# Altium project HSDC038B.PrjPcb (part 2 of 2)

## Sheet HSDC038B_Magnetics.SchDoc
size 431 x 279 mm; Date: Not shown in title block; ApprovedBy: Not shown in title block; CheckedBy: Not shown in title block; Author: Not shown in title block; CompanyName: Not shown in title block; Engineer: Not shown in title block; Organization: Not shown in title block; Address1: Not shown in title block; Address2: Not shown in title block; Address3: Not shown in title block; Address4: Not shown in title block; DocumentNumber: 4; Revision: Use project parameter SCH_Rev; SheetNumber: 4; SheetTotal: 7; PageSetup: Record=PageOptions¦CenterHorizontal=True¦CenterVertical=True¦PrintScale=1.00¦XCorrection=1.00¦YCorrection=1.00¦PrintKind=0¦BorderSize=5000000¦LeftOffset=0¦BottomOffset=0¦Orientation=2¦PaperLength=1000¦PaperWidth=1000¦Scale=100¦PaperSource=15¦PrintQuality=600¦MediaType=1¦DitherType=10¦PaperKind=Letter¦PrintScaleMode=1
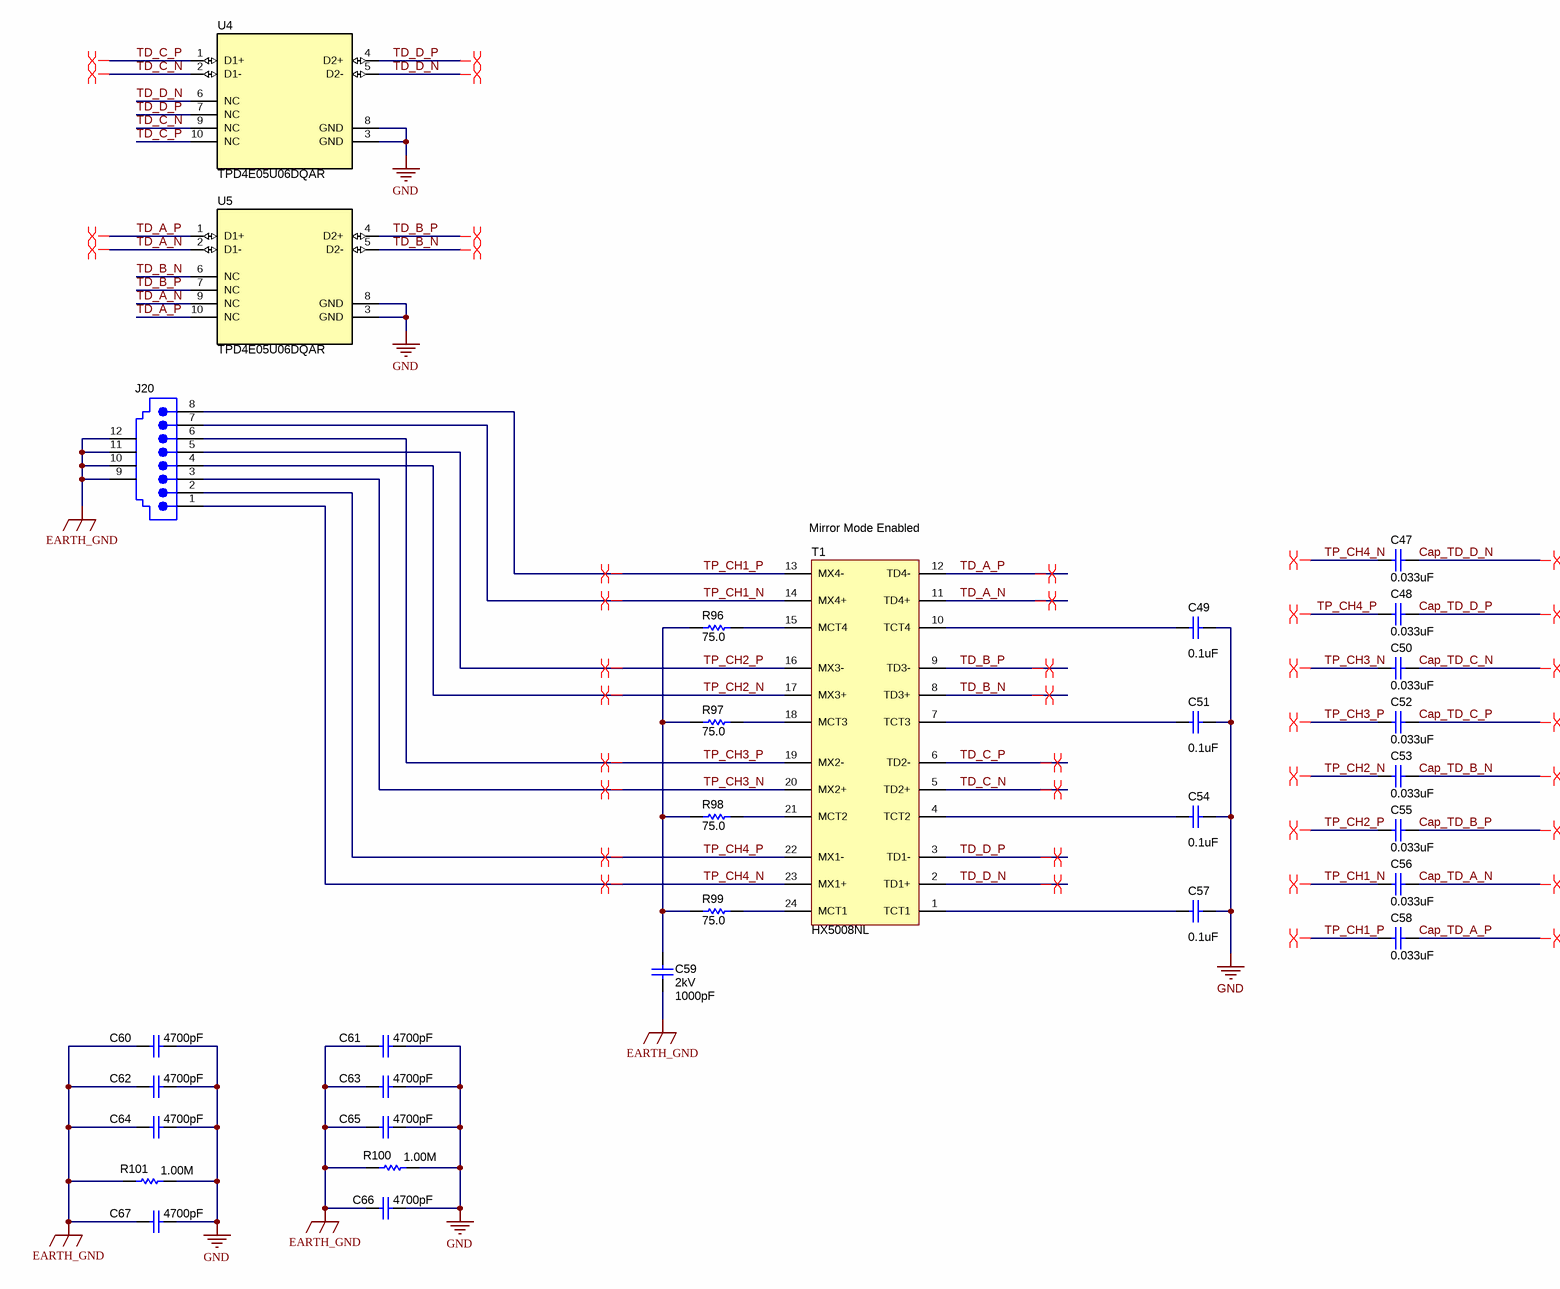
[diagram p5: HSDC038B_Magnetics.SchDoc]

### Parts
C47  ValueDisplayed: 0.033uF  [0402L]  (hidden comment: GRM155R61A333KA01D)
C48  ValueDisplayed: 0.033uF  [0402L]  (hidden comment: GRM155R61A333KA01D)
C49  ValueDisplayed: 0.1uF  [0603]  (hidden comment: C0603C104K8RACTU)
C50  ValueDisplayed: 0.033uF  [0402L]  (hidden comment: GRM155R61A333KA01D)
C51  ValueDisplayed: 0.1uF  [0603]  (hidden comment: C0603C104K8RACTU)
C52  ValueDisplayed: 0.033uF  [0402L]  (hidden comment: GRM155R61A333KA01D)
C53  ValueDisplayed: 0.033uF  [0402L]  (hidden comment: GRM155R61A333KA01D)
C54  ValueDisplayed: 0.1uF  [0603]  (hidden comment: C0603C104K8RACTU)
C55  ValueDisplayed: 0.033uF  [0402L]  (hidden comment: GRM155R61A333KA01D)
C56  ValueDisplayed: 0.033uF  [0402L]  (hidden comment: GRM155R61A333KA01D)
C57  ValueDisplayed: 0.1uF  [0603]  (hidden comment: C0603C104K8RACTU)
C58  ValueDisplayed: 0.033uF  [0402L]  (hidden comment: GRM155R61A333KA01D)
C59  VDC_V: 2kV  ValueDisplayed: 1000pF  [1808]  (hidden comment: GR442QR73D102KW01L)
C60  ValueDisplayed: 4700pF  [1812_254]  (hidden comment: 1812GC472KAT1A)
C61  ValueDisplayed: 4700pF  [1812_254]  (hidden comment: 1812GC472KAT1A)
C62  ValueDisplayed: 4700pF  [1812_254]  (hidden comment: 1812GC472KAT1A)
C63  ValueDisplayed: 4700pF  [1812_254]  (hidden comment: 1812GC472KAT1A)
C64  ValueDisplayed: 4700pF  [1812_254]  (hidden comment: 1812GC472KAT1A)
C65  ValueDisplayed: 4700pF  [1812_254]  (hidden comment: 1812GC472KAT1A)
C66  ValueDisplayed: 4700pF  [1812_254]  (hidden comment: 1812GC472KAT1A)
C67  ValueDisplayed: 4700pF  [1812_254]  (hidden comment: 1812GC472KAT1A)
J20  1-406541-1  [TEC_1-406541-1]  (value not drawn)
R96  ValueDisplayed: 75.0  [0805_HV]  (hidden comment: CRCW080575R0FKEA)
R97  ValueDisplayed: 75.0  [0805_HV]  (hidden comment: CRCW080575R0FKEA)
R98  ValueDisplayed: 75.0  [0805_HV]  (hidden comment: CRCW080575R0FKEA)
R99  ValueDisplayed: 75.0  [0805_HV]  (hidden comment: CRCW080575R0FKEA)
R100  ValueDisplayed: 1.00M  [2010]  (hidden comment: HVCB2010FKC1M00)
R101  ValueDisplayed: 1.00M  [2010]  (hidden comment: HVCB2010FKC1M00)
T1  HX5008NL  [PULSE_HX5008NL]
U4  TPD4E05U06DQAR  [DQA0010A]
U5  TPD4E05U06DQAR  [DQA0010A]

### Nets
EARTH_GND: C59.2 C60.2 C61.2 C62.2 C63.2 C64.2 C65.2 C66.2 C67.2 J20.9 J20.10 J20.11 J20.12 R100.1 R101.1
GND: C49.1 C51.1 C54.1 C57.1 C60.1 C61.1 C62.1 C63.1 C64.1 C65.1 C66.1 C67.1 R100.2 R101.2 U4.3(GND) U4.8(GND) U5.3(GND) U5.8(GND)
Cap_TD_A_N: C56.2
Cap_TD_A_P: C58.2
Cap_TD_B_N: C53.2
Cap_TD_B_P: C55.2
Cap_TD_C_N: C50.2
Cap_TD_C_P: C52.2
Cap_TD_D_N: C47.2
Cap_TD_D_P: C48.2
TD_A_N: T1.11(TD4+) U5.2(D1-) U5.9(NC)
TD_A_P: T1.12(TD4-) U5.1(D1+) U5.10(NC)
TD_B_N: T1.8(TD3+) U5.5(D2-) U5.6(NC)
TD_B_P: T1.9(TD3-) U5.4(D2+) U5.7(NC)
TD_C_N: T1.5(TD2+) U4.2(D1-) U4.9(NC)
TD_C_P: T1.6(TD2-) U4.1(D1+) U4.10(NC)
TD_D_N: T1.2(TD1+) U4.5(D2-) U4.6(NC)
TD_D_P: T1.3(TD1-) U4.4(D2+) U4.7(NC)
TP_CH1_N: C56.1 J20.7 T1.14(MX4+)
TP_CH1_P: C58.1 J20.8 T1.13(MX4-)
TP_CH2_N: C53.1 J20.4 T1.17(MX3+)
TP_CH2_P: C55.1 J20.5 T1.16(MX3-)
TP_CH3_N: C50.1 J20.3 T1.20(MX2+)
TP_CH3_P: C52.1 J20.6 T1.19(MX2-)
TP_CH4_N: C47.1 J20.1 T1.23(MX1+)
TP_CH4_P: C48.1 J20.2 T1.22(MX1-)
NetC49_2: C49.2 T1.10(TCT4)
NetC51_2: C51.2 T1.7(TCT3)
NetC54_2: C54.2 T1.4(TCT2)
NetC57_2: C57.2 T1.1(TCT1)
NetC59_1: C59.1 R96.1 R97.1 R98.1 R99.1
NetR96_2: R96.2 T1.15(MCT4)
NetR97_2: R97.2 T1.18(MCT3)
NetR98_2: R98.2 T1.21(MCT2)
NetR99_2: R99.2 T1.24(MCT1)

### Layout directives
differential pair: Cap_TD_A_N, Cap_TD_A_P, Cap_TD_B_N, Cap_TD_B_P, Cap_TD_C_N, Cap_TD_C_P, Cap_TD_D_N, Cap_TD_D_P, TD_A_N, TD_A_P, TD_B_N, TD_B_P, TD_C_N, TD_C_P, TD_D_N, TD_D_P, TP_CH1_N, TP_CH1_P, TP_CH2_N, TP_CH2_P, TP_CH3_N, TP_CH3_P, TP_CH4_N, TP_CH4_P

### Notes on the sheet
- (near T1) Mirror Mode Enabled

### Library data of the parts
C47 C48 C50 C52 C53 C55 C56 C58 = CMP-0006574-2: CAP, CERM, 0.033 uF, 10 V, +/- 10%, X5R, 0402; Manufacturer: MuRata; TaMin_C: -55°C; Polarized: N; SizeAreaWB_mm2: 3; Value1: Unknown; U/M: EA; TaMax_C: 85°C; SizeZ_mm: 0.6; SizeX_mm: 1; SizeY_mm: 0.5; Cap_Case: 0402; Value2: 10V; CompType: Capacitor; Cap_F: 33nF; AEC Category: Q200
C49 C51 C54 C57 = CMP-0006862-2: CAP, CERM, 0.1 uF, 10 V, +/- 10%, X7R, 0603; Manufacturer: Kemet; TaMin_C: -55°C; Polarized: N; SizeAreaWB_mm2: 4.68; Value1: Unknown; U/M: EA; Value: 0.1uF; TaMax_C: 125°C; SizeZ_mm: 1; SizeX_mm: 1.6; SizeY_mm: 0.8; Value2: 10V; SizeArea_mm2: 1.28; CompType: Capacitor; Cap_F: 100nF; AEC Category: Q200
C59 = CMP-0009436-2: CAP, CERM, 1000 pF, 2000 V, +/- 10%, X7R, 1808; Manufacturer: MuRata; TaMin_C: -55°C; Polarized: N; SizeAreaWB_mm2: 16.5; Value1: Unknown; U/M: EA; Value: 1000pF; TaMax_C: 125°C; SizeZ_mm: 2.03; SizeX_mm: 4.5; SizeY_mm: 2; Value2: 2000V; SizeArea_mm2: 9; Cap_F: 1nF; AEC Category: Q200
C60-C67 = CMP-0009295-2: CAP, CERM, 4700 pF, 2000 V, +/- 10%, X7R, 1812; Manufacturer: AVX; Polarized: N; Value: 4700pF; U/M: EA; Cap_F: 4.7nF; Value1: Unknown; VDC_V: 2kV; Value2: 2000V; TaMin_C: -55°C; TaMax_C: 125°C; Cap_Case: 1812; AEC Category: Q200; SizeArea_mm2: 14.4; SizeAreaWB_mm2: 23.1; SizeX_mm: 4.5; SizeY_mm: 3.2; SizeZ_mm: 2.54
J20 = CMP-0054918-1: RJ45, No LED, tab up, R/A, TH; Manufacturer: TE Connectivity; CNHeader: FALSE; ContactFinish: Gold; CT: TRUE; Green_Lifecycle: Active; Green_REACh: Passed
R96-R99 = CMP-0021425-2: RES, 75.0, 1%, 0.125 W, 0805; Manufacturer: Vishay-Dale; Power_W: 125mW; TempCo: 100 ppm/C; Value_Code: 75R0; U/M: EA; Value: 75.0; EIA_Code: E96; Res_ohm: 75; SizeX_mm: 2; SizeY_mm: 1.25; SizeZ_mm: 1.45; Value2: 0.125W; SizeArea_mm2: 2.5; VDC_V: 150V; AEC Category: Q200
R100 R101 = CMP-0016535-2: RES, 1.00 M, 1%, 1 W, 2010; Manufacturer: Stackpole Electronics Inc; Power_W: 1W; TempCo: 50 ppm/C; Value_Code: 1M00; U/M: EA; Value: 1.00Meg; EIA_Code: E96; Res_ohm: 1M; SizeX_mm: 5; SizeY_mm: 2.5; SizeZ_mm: 1.66; SizeArea_mm2: 12.5; AEC Qualified: N; VDC_V: 2kV; AEC Category: Q200
T1 = CMP-0030394-2: Transformer, 325 uH, SMT; Manufacturer: Pulse Engineering; Value: 325uH; Lp: 325; Ind_H: 325µH
U4 U5 = CMP-0073613-2: 4-Channel Ultra-Low-Capacitance IEC ESD Protection Diode, DQA0010A (USON-10); Manufacturer: Texas Instruments; CompType: IC; U/M: EA; Green_Lifecycle: Active; Green_REACh: Passed; SizeArea_mm2: 2.5; SizeAreaWB_mm2: 7.0; SizeX_mm: 1.0; SizeZ_mm: 0.55

## Sheet HSDC038B_Power_Supply.SchDoc
size 431 x 279 mm; Date: Not shown in title block; ApprovedBy: Not shown in title block; CheckedBy: Not shown in title block; Author: Not shown in title block; CompanyName: Not shown in title block; Engineer: Not shown in title block; Organization: Not shown in title block; Address1: Not shown in title block; Address2: Not shown in title block; Address3: Not shown in title block; Address4: Not shown in title block; DocumentNumber: 5; Revision: Use project parameter SCH_Rev; SheetNumber: 5; SheetTotal: 7; PageSetup: Record=PageOptions¦CenterHorizontal=True¦CenterVertical=True¦PrintScale=1.00¦XCorrection=1.00¦YCorrection=1.00¦PrintKind=0¦BorderSize=5000000¦LeftOffset=0¦BottomOffset=0¦Orientation=2¦PaperLength=1000¦PaperWidth=1000¦Scale=100¦PaperSource=15¦PrintQuality=600¦MediaType=1¦DitherType=10¦PaperKind=Letter¦PrintScaleMode=1
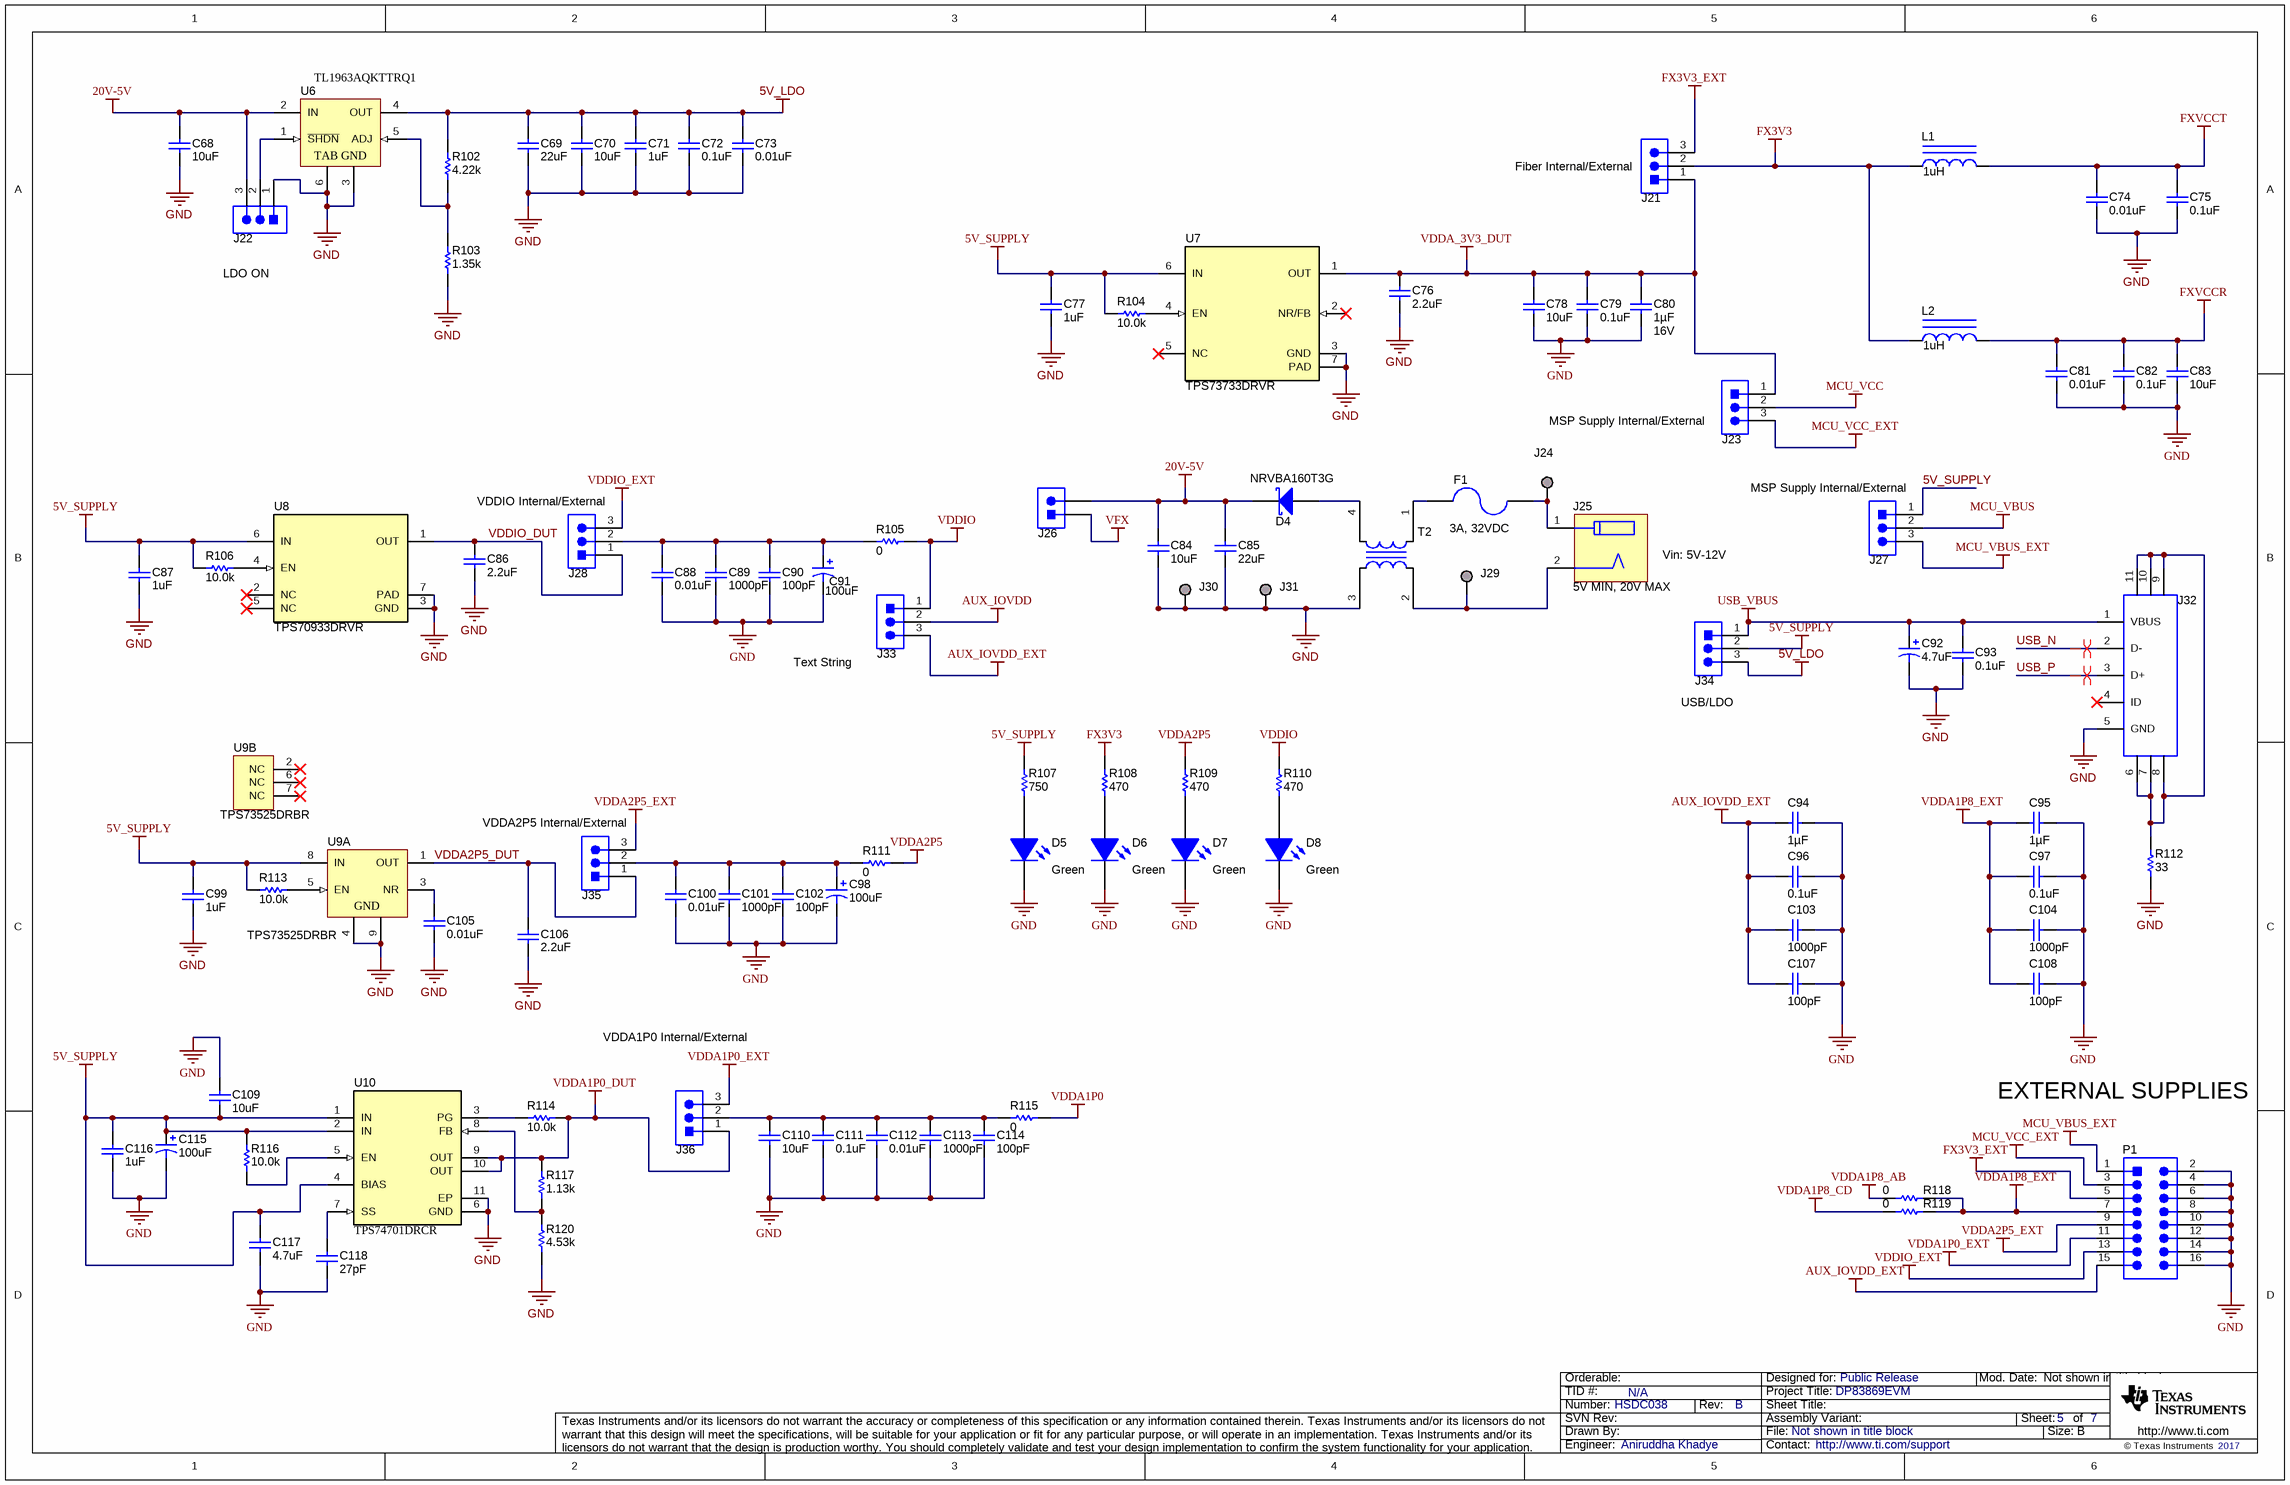
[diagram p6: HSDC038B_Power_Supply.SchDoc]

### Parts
C68  ValueDisplayed: 10uF  [1210_280]  (hidden comment: CGA6P1X7R1E106M250AC)
C69  ValueDisplayed: 22uF  [1210_280]  (hidden comment: CGA6P1X7R1C226M250AC)
C70  ValueDisplayed: 10uF  [1210_280]  (hidden comment: CGA6P1X7R1E106M250AC)
C71  ValueDisplayed: 1uF  [0805_HV]  (hidden comment: GRM216R61C105KA88D)
C72  ValueDisplayed: 0.1uF  [0805_HV]  (hidden comment: GCM21BR71H104KA37K)
C73  ValueDisplayed: 0.01uF  [0402]  (hidden comment: CGA2B3X7R1H103K050BB)
C74  ValueDisplayed: 0.01uF  [0402]  (hidden comment: CGA2B3X7R1H103K050BB)
C75  ValueDisplayed: 0.1uF  [0402]  (hidden comment: GRM155R71C104KA88D)
C76  ValueDisplayed: 2.2uF  [0603]  (hidden comment: CGA3E1X7S1C225M080AC)
C77  ValueDisplayed: 1uF  [0402]  (hidden comment: GRM155R6YA105ME11D)
C78  ValueDisplayed: 10uF  [1206_190]  (hidden comment: C3216X7R1V106M160AC)
C79  ValueDisplayed: 0.1uF  [0603]  (hidden comment: CL10B104KO8NNNC)
C80  ValueDisplayed: 1µF  VDC_V: 16V  [0402]  (hidden comment: GRM155R61C105MA12D)
C81  ValueDisplayed: 0.01uF  [0402]  (hidden comment: CGA2B3X7R1H103K050BB)
C82  ValueDisplayed: 0.1uF  [0402]  (hidden comment: GRM155R71C104KA88D)
C83  ValueDisplayed: 10uF  [1206_190]  (hidden comment: C3216X7R1V106M160AC)
C84  ValueDisplayed: 10uF  [1210_280]  (hidden comment: CGA6P1X7R1E106M250AC)
C85  ValueDisplayed: 22uF  [1210_280]  (hidden comment: CGA6P1X7R1C226M250AC)
C86  ValueDisplayed: 2.2uF  [0603]  (hidden comment: CGA3E1X7S1C225M080AC)
C87  ValueDisplayed: 1uF  [0402]  (hidden comment: GRM155R6YA105ME11D)
C88  ValueDisplayed: 0.01uF  [0603]  (hidden comment: C0603C103J5RACTU)
C89  ValueDisplayed: 1000pF  [0603]  (hidden comment: 06035A102KAT2A)
C90  ValueDisplayed: 100pF  [0402]  (hidden comment: CC0402JRNPO9BN101)
C91  ValueDisplayed: 100uF  [7343-31]  (hidden comment: 593D107X0010D2TE3)
C92  ValueDisplayed: 4.7uF  [7343-31]  (hidden comment: 293D475X9035D2TE3)
C93  ValueDisplayed: 0.1uF  [0402]  (hidden comment: GRM155R71C104KA88D)
C94  ValueDisplayed: 1µF  [0402]  (hidden comment: GRM155R61C105MA12D)
C95  ValueDisplayed: 1µF  [0402]  (hidden comment: GRM155R61C105MA12D)
C96  ValueDisplayed: 0.1uF  [0402]  (hidden comment: C1005X5R1A104K050BA)
C97  ValueDisplayed: 0.1uF  [0402]  (hidden comment: C1005X5R1A104K050BA)
C98  ValueDisplayed: 100uF  [7343-31]  (hidden comment: 593D107X0010D2TE3)
C99  ValueDisplayed: 1uF  [0402]  (hidden comment: GRM155R6YA105ME11D)
C100  ValueDisplayed: 0.01uF  [0603]  (hidden comment: C0603C103J5RACTU)
C101  ValueDisplayed: 1000pF  [0603]  (hidden comment: 06035A102KAT2A)
C102  ValueDisplayed: 100pF  [0402]  (hidden comment: CC0402JRNPO9BN101)
C103  ValueDisplayed: 1000pF  [0402]  (hidden comment: GRM155R61E102KA01D)
C104  ValueDisplayed: 1000pF  [0402]  (hidden comment: GRM155R61E102KA01D)
C105  ValueDisplayed: 0.01uF  [0603]  (hidden comment: C0603C103J5RACTU)
C106  ValueDisplayed: 2.2uF  [0603]  (hidden comment: CGA3E1X7S1C225M080AC)
C107  ValueDisplayed: 100pF  [0402]  (hidden comment: CC0402JRNPO9BN101)
C108  ValueDisplayed: 100pF  [0402]  (hidden comment: CC0402JRNPO9BN101)
C109  ValueDisplayed: 10uF  [1206_190]  (hidden comment: C3216X7R1V106M160AC)
C110  ValueDisplayed: 10uF  [1206_190]  (hidden comment: C3216X7R1V106M160AC)
C111  ValueDisplayed: 0.1uF  [0603L]  (hidden comment: CL10B104KO8NNNC)
C112  ValueDisplayed: 0.01uF  [0603L]  (hidden comment: C0603C103J5RACTU)
C113  ValueDisplayed: 1000pF  [0603L]  (hidden comment: 06035A102KAT2A)
C114  ValueDisplayed: 100pF  [0402]  (hidden comment: CC0402JRNPO9BN101)
C115  ValueDisplayed: 100uF  [7343-31]  (hidden comment: 593D107X0010D2TE3)
C116  ValueDisplayed: 1uF  [0805_HV]  (hidden comment: 0805YD105KAT2A)
C117  ValueDisplayed: 4.7uF  [0805_HV]  (hidden comment: CC0805ZRY5V6BB475)
C118  ValueDisplayed: 27pF  [0603L]  (hidden comment: CL10C270FB8NNNC)
D4  NRVBA160T3G  [SMA]
D5  value Green  [QTLP630C_Green]  (hidden comment: QTLP630C4TR)
D6  value Green  [QTLP630C_Green]  (hidden comment: QTLP630C4TR)
D7  value Green  [QTLP630C_Green]  (hidden comment: QTLP630C4TR)
D8  value Green  [QTLP630C_Green]  (hidden comment: QTLP630C4TR)
F1  F0603E3R00FSTR  [0603]  (value not drawn)
J21  HTSW-103-07-G-S  [Samtec_HTSW-103-07-G-S]  (value not drawn)
J22  HTSW-103-07-G-S  [Samtec_HTSW-103-07-G-S]  (value not drawn)
J23  HTSW-103-07-G-S  [Samtec_HTSW-103-07-G-S]  (value not drawn)
J24  1502-2  [Keystone1502-2]  (value not drawn)
J25  5V MIN, 20V MAX  [CUI_PJ-037AH]
J26  HTSW-102-07-G-S  [Samtec_HTSW-102-07-G-S]  (value not drawn)
J27  HTSW-103-07-G-S  [Samtec_HTSW-103-07-G-S]  (value not drawn)
J28  HTSW-103-07-G-S  [Samtec_HTSW-103-07-G-S]  (value not drawn)
J29  1502-2  [Keystone1502-2]  (value not drawn)
J30  GND  [Keystone1502-2]  (value not drawn)
J31  GND  [Keystone1502-2]  (value not drawn)
J32  475890001  [Molex_0475890001]  (value not drawn)
J33  HTSW-103-07-G-S  [Samtec_HTSW-103-07-G-S]  (value not drawn)
J34  HTSW-103-07-G-S  [Samtec_HTSW-103-07-G-S]  (value not drawn)
J35  HTSW-103-07-G-S  [Samtec_HTSW-103-07-G-S]  (value not drawn)
J36  HTSW-103-07-G-S  [Samtec_HTSW-103-07-G-S]  (value not drawn)
L1  value 1uH  [IFSC-0806AZ-01]  (hidden comment: IFSC0806AZER1R0M01)
L2  value 1uH  [IFSC-0806AZ-01]  (hidden comment: IFSC0806AZER1R0M01)
P1  TSW-108-07-G-D  [TSW-108-07-G-D]  (value not drawn)
R102  ValueDisplayed: 4.22k  [0603]  (hidden comment: CRCW06034K22FKEA)
R103  ValueDisplayed: 1.35k  [0603]  (hidden comment: RT0603BRD071K35L)
R104  ValueDisplayed: 10.0k  [0402]  (hidden comment: CRCW040210K0FKED)
R105  ValueDisplayed: 0  [0805_HV]  (hidden comment: ERJ-6GEY0R00V)
R106  ValueDisplayed: 10.0k  [0402]  (hidden comment: CRCW040210K0FKED)
R107  ValueDisplayed: 750  [0402]  (hidden comment: CRCW0402750RJNED)
R108  ValueDisplayed: 470  [0402]  (hidden comment: CRCW0402470RJNED)
R109  ValueDisplayed: 470  [0402]  (hidden comment: CRCW0402470RJNED)
R110  ValueDisplayed: 470  [0402]  (hidden comment: CRCW0402470RJNED)
R111  ValueDisplayed: 0  [0805_HV]  (hidden comment: ERJ-6GEY0R00V)
R112  ValueDisplayed: 33  [0402]  (hidden comment: CRCW040233R0JNED)
R113  ValueDisplayed: 10.0k  [0402]  (hidden comment: CRCW040210K0FKED)
R114  ValueDisplayed: 10.0k  [0603]  (hidden comment: RC0603FR-0710KL)
R115  ValueDisplayed: 0  [0805_HV]  (hidden comment: ERJ-6GEY0R00V)
R116  ValueDisplayed: 10.0k  [0402]  (hidden comment: CRCW040210K0FKED)
R117  ValueDisplayed: 1.13k  [0603]  (hidden comment: CRCW06031K13FKEA)
R118  ValueDisplayed: 0  [0603]  (hidden comment: RC0603JR-070RL)
R119  ValueDisplayed: 0  [0603]  (hidden comment: RC0603JR-070RL)
R120  ValueDisplayed: 4.53k  [0603]  (hidden comment: CRCW06034K53FKEA)
T2  ACM9070-701-2PL-TL01  [TDK_ACM9070]  (value not drawn)
U6  TL1963AQKTTRQ1  [KTT0005A_N]
U7  TPS73733DRVR  [DRV0006A]
U8  TPS70933DRVR  [DRV0006A]
U9  TPS73525DRBR  [DRB0008A]  (parts A,B of 2)
U10  TPS74701DRCR  [DRC0010J]

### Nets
5V_LDO: C69.1 C70.1 C71.1 C72.1 C73.1 J34.3 R102.2 U6.4(OUT)
5V_SUPPLY: C77.1 C87.1 C99.1 C109.2 C115.1(+) C116.2 C117.1 J27.1 J34.2 R104.2 R106.2 R107.2 R113.2 R116.1 U7.6(IN) U8.6(IN) U9.8(IN) U10.1(IN) U10.2(IN) U10.4(BIAS)
20V-5V: C68.1 C84.1 C85.1 D4.1(K) J22.3 J26.2 U6.2(IN)
AUX_IOVDD: J33.2
AUX_IOVDD_EXT: C94.2 C96.2 C103.2 C107.2 J33.3 P1.15
FX3V3: J21.2 L1.1 L2.1 R108.2
FX3V3_EXT: J21.3 P1.5
FXVCCR: C81.1 C82.1 C83.1 L2.2
FXVCCT: C74.1 C75.1 L1.2
GND: C68.2 C69.2 C70.2 C71.2 C72.2 C73.2 C74.2 C75.2 C76.1 C77.2 C78.2 C79.2 C80.2 C81.2 C82.2 C83.2 C84.2 C85.2 C86.1 C87.2 C88.1 C89.1 C90.1 C91.2(-) C92.2(-) C93.1 C94.1 C95.1 C96.1 C97.1 C98.2(-) C99.2 C100.1 C101.1 C102.1 C103.1 C104.1 C105.1 C106.1 C107.1 C108.1 C109.1 C110.2 C111.2 C112.1 C113.1 C114.1 C115.2(-) C116.1 C117.2 C118.1 D5.2(K) D6.2(K) D7.2(K) D8.2(K) J22.1 J30.1 J31.1 J32.5(GND) P1.2 P1.4 P1.6 P1.8 P1.10 P1.12 P1.14 P1.16 R103.1 R112.2 R120.1 T2.3 U6.3(GND) U6.6(TAB) U7.3(GND) U7.7(PAD) U8.3(GND) U8.7(PAD) U9.4(GND) U9.9(GND) U10.6(GND) U10.11(EP)
MCU_VBUS: J27.2
MCU_VBUS_EXT: J27.3 P1.1
MCU_VCC: J23.2
MCU_VCC_EXT: J23.3 P1.3
USB_VBUS: C92.1(+) C93.2 J32.1(VBUS) J34.1
VDDA1P0: R115.2
VDDA1P0_DUT: J36.1 R114.1 R117.2 U10.9(OUT) U10.10(OUT)
VDDA1P0_EXT: J36.3 P1.11
VDDA1P8_AB: R118.1
VDDA1P8_CD: R119.1
VDDA1P8_EXT: C95.2 C97.2 C104.2 C108.2 P1.7 R118.2 R119.2
VDDA2P5: R109.2 R111.2
VDDA2P5_EXT: J35.3 P1.9
VDDA_3V3_DUT: C76.2 C78.1 C79.1 C80.1 J21.1 J23.1 U7.1(OUT)
VDDIO: J33.1 R105.2 R110.2
VDDIO_EXT: J28.3 P1.13
VFX: J26.1
USB_N: J32.2(D-)
USB_P: J32.3(D+)
VDDA2P5_DUT: C106.2 J35.1 U9.1(OUT)
VDDIO_DUT: C86.2 J28.1 U8.1(OUT)
NetC88_2: C88.2 C89.2 C90.2 C91.1(+) J28.2 R105.1
NetC98_1: C98.1(+) C100.2 C101.2 C102.2 J35.2 R111.1
NetC105_2: C105.2 U9.3(NR)
NetC110_1: C110.1 C111.1 C112.2 C113.2 C114.2 J36.2 R115.1
NetC118_2: C118.2 U10.7(SS)
NetD4_2: D4.2(A) T2.4
NetD5_1: D5.1(A) R107.1
NetD6_1: D6.1(A) R108.1
NetD7_1: D7.1(A) R109.1
NetD8_1: D8.1(A) R110.1
NetF1_1: F1.1 J24.1 J25.1
NetF1_2: F1.2 T2.1
NetJ22_2: J22.2 U6.1(~{SHDN})
NetJ25_2: J25.2 J29.1 T2.2
NetJ32_6: J32.6 J32.7 J32.8 J32.9 J32.10 J32.11 R112.1
NetR102_1: R102.1 R103.2 U6.5(ADJ)
NetR104_1: R104.1 U7.4(EN)
NetR106_1: R106.1 U8.4(EN)
NetR113_1: R113.1 U9.5(EN)
NetR114_2: R114.2 U10.3(PG)
NetR116_2: R116.2 U10.5(EN)
NetR117_1: R117.1 R120.2 U10.8(FB)

Not connected (* = marked no-connect by the designer): J32 4(ID)*; U7 2(NR/FB)* 5(NC)*; U8 2(NC)* 5(NC)*; U9 2(NC)* 6(NC)* 7(NC)*

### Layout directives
differential pair: USB_N, USB_P

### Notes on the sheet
- (near J21) Fiber Internal/External
- LDO ON
- (near J23) MSP Supply Internal/External
- (near J28) VDDIO Internal/External
- (near J27) MSP Supply Internal/External
- (near F1) 3A, 32VDC
- Vin: 5V-12V
- Text String
- (near J34) USB/LDO
- (near J35) VDDA2P5 Internal/External
- VDDA1P0 Internal/External
- EXTERNAL SUPPLIES

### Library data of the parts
C68 C70 C84 = CMP-0009155-2: CAP, CERM, 10 uF, 25 V, +/- 20%, X7R, AEC-Q200 Grade 1, 1210; Manufacturer: TDK; Polarized: N; Value: 10uF; U/M: EA; Cap_F: 10µF; Value1: Unknown; VDC_V: 25V; TaMin_C: -55°C; TaMax_C: 125°C; Cap_Case: 1210; AEC Category: Q200; AEC Qualified: Y; AEC Grade: 1; SizeArea_mm2: 8; SizeAreaWB_mm2: 14.7; SizeX_mm: 3.2; SizeY_mm: 2.5; SizeZ_mm: 2.8
C69 C85 = CMP-0009154-2: CAP, CERM, 22 uF, 16 V, +/- 20%, X7R, AEC-Q200 Grade 1, 1210; Manufacturer: TDK; Polarized: N; Value: 22uF; U/M: EA; Cap_F: 22µF; ESR_ohm: 2.582m; Value1: 0.002582 ohm; VDC_V: 16V; IRMS_A: 4.57562A; TaMin_C: -55°C; TaMax_C: 125°C; AEC Category: Q200; AEC Qualified: Y; AEC Grade: 1; SizeArea_mm2: 8; SizeAreaWB_mm2: 14.7; SizeX_mm: 3.2; SizeY_mm: 2.5; SizeZ_mm: 2.8
C71 = CMP-0008135-2: CAP, CERM, 1 uF, 16 V, +/- 10%, X5R, 0805; Manufacturer: MuRata; Polarized: N; Value: 1uF; U/M: EA; Cap_F: 1µF; Value1: Unknown; VDC_V: 16V; TaMin_C: -55°C; TaMax_C: 85°C; Cap_Case: 0805; AEC Category: Q200; SizeArea_mm2: 2.5; SizeAreaWB_mm2: 6.75; SizeX_mm: 2; SizeY_mm: 1.25; SizeZ_mm: 1.45
C72 = CMP-0008021-2: CAP, CERM, 0.1 uF, 50 V, +/- 10%, X7R, AEC-Q200 Grade 1, 0805; Manufacturer: MuRata; Polarized: N; CompType: Capacitor; Value: 0.1uF; U/M: EA; Cap_F: 100nF; Value1: Unknown; VDC_V: 50V; TaMin_C: -55°C; TaMax_C: 125°C; Cap_Case: 0805; AEC Category: Q200; AEC Qualified: Y; AEC Grade: 1; SizeArea_mm2: 2.5; SizeAreaWB_mm2: 6.75; SizeX_mm: 2; SizeY_mm: 1.25; SizeZ_mm: 1.45
C73 C74 C81 = CMP-0006324-2: CAP, CERM, 0.01 uF, 50 V, +/- 10%, X7R, AEC-Q200 Grade 1, 0402; Manufacturer: TDK; Polarized: N; Value: 0.01uF; U/M: EA; Cap_F: 10nF; ESR_ohm: 3.33065d; Value1: 0.333065 ohm; VDC_V: 50V; IRMS_A: 3.23373dA; TaMin_C: -55°C; TaMax_C: 125°C; AEC Category: Q200; AEC Qualified: Y; AEC Grade: 1; SizeArea_mm2: 0.5; SizeAreaWB_mm2: 3; SizeZ_mm: 0.6
C75 C82 C93 = CMP-0006641-2: CAP, CERM, 0.1 uF, 16 V, +/- 10%, X7R, 0402; Manufacturer: MuRata; Polarized: N; Value: 0.1uF; U/M: EA; Cap_F: 100nF; Value1: Unknown; VDC_V: 16V; TaMin_C: -55°C; TaMax_C: 125°C; AEC Category: Q200; SizeArea_mm2: 0.5; SizeAreaWB_mm2: 3; SizeX_mm: 1; SizeZ_mm: 0.6
C76 C86 C106 = CMP-0007068-4: CAP, CERM, 2.2 uF, 16 V, +/- 20%, X7S, AEC-Q200 Grade 1, 0603; Manufacturer: TDK; Polarized: N; Value: 2.2uF; U/M: EA; Cap_F: 2.2µF; Value1: Unknown; VDC_V: 16V; TaMin_C: -55°C; TaMax_C: 125°C; SizeArea_mm2: 1.28; SizeAreaWB_mm2: 4.68; SizeX_mm: 1.6; SizeY_mm: 0.8; SizeZ_mm: 1; AEC Category: Q200; AEC Qualified: Y
C77 C87 C99 = CMP-0006620-2: CAP, CERM, 1 uF, 35 V, +/- 20%, X5R, 0402; Manufacturer: MuRata; TaMin_C: -55°C; Polarized: N; SizeAreaWB_mm2: 3; Value1: Unknown; U/M: EA; Value: 1uF; TaMax_C: 85°C; SizeZ_mm: 0.6; SizeX_mm: 1; SizeY_mm: 0.5; Value2: 35V; CompType: Capacitor; Cap_F: 1µF; AEC Category: Q200
C78 C83 C109 C110 = CMP-0008706-2: CAP, CERM, 10 uF, 35 V, +/- 20%, X7R, 1206_190; Manufacturer: TDK; Polarized: N; Value: 10uF; U/M: EA; Cap_F: 10µF; Value1: Unknown; VDC_V: 35V; TaMin_C: -55°C; TaMax_C: 125°C; Cap_Case: 1206; AEC Category: Q200; SizeArea_mm2: 5.12; SizeAreaWB_mm2: 10.92; SizeX_mm: 3.2; SizeY_mm: 1.6; SizeZ_mm: 1.9
C79 = CMP-0007110-5: CAP, CERM, 0.1 uF, 16 V, +/- 10%, X7R, 0603; Manufacturer: Samsung Electro-Mechanics; Polarized: N; Value: 0.1uF; U/M: EA; Cap_F: 100nF; Value1: Unknown; VDC_V: 16V; TaMin_C: -55°C; TaMax_C: 125°C; AEC Category: Q200; SizeArea_mm2: 1.28; SizeAreaWB_mm2: 4.68; SizeX_mm: 1.6; SizeY_mm: 0.8; SizeZ_mm: 1
C80 = CMP-0084375-1: CAP, CERM, 1 µF, 16 V,+/- 20%, X5R, 0402; Manufacturer: MuRata; Polarized: N; Value: 1uF; U/M: EA; TaMin_C: -55°C; TaMax_C: 85°C; AEC Category: Q200; SizeArea_mm2: 0.5; SizeAreaWB_mm2: 3; SizeX_mm: 1; SizeZ_mm: 0.6
C88 C100 C105 = CMP-0006850-4: CAP, CERM, 0.01 uF, 50 V, +/- 5%, X7R, 0603; Manufacturer: Kemet; Polarized: N; Value: 0.01uF; U/M: EA; Cap_F: 10nF; Value1: Unknown; VDC_V: 50V; TaMin_C: -55°C; TaMax_C: 125°C; AEC Category: Q200; SizeArea_mm2: 1.28; SizeAreaWB_mm2: 4.68; SizeX_mm: 1.6; SizeY_mm: 0.8; SizeZ_mm: 1
C89 C101 = CMP-0006764-4: CAP, CERM, 1000 pF, 50 V, +/- 10%, C0G/NP0, 0603; Manufacturer: AVX; Polarized: N; Value: 1000pF; U/M: EA; Cap_F: 1nF; ESR_ohm: 0.048; Value1: 0.048 ohm; VDC_V: 50V; TaMin_C: -55°C; TaMax_C: 125°C; AEC Category: Q200; SizeArea_mm2: 1.28; SizeAreaWB_mm2: 4.68; SizeX_mm: 1.6; SizeY_mm: 0.8; SizeZ_mm: 1
C90 C102 C107 C108 C114 = CMP-0006303-2: CAP, CERM, 100 pF, 50 V, +/- 5%, C0G/NP0, 0402; Manufacturer: Yageo America; Polarized: N; Value: 100pF; U/M: EA; Value1: Unknown; VDC_V: 50V; TaMin_C: -55°C; TaMax_C: 125°C; AEC Category: Q200; SizeArea_mm2: 0.5; SizeAreaWB_mm2: 3; SizeX_mm: 1; SizeZ_mm: 0.6
C91 C98 C115 = CMP-0011720-2: CAP, TA, 100 uF, 10 V, +/- 20%, 0.1 ohm, SMD; Manufacturer: Vishay-Sprague; Polarized: Y; CompType: Capacitor; Value: 100uF; U/M: EA; Cap_F: 100µF; Value1: 0.1 ohm; VDC_V: 10V; ESR_ohm: 1d; IRMS_A: 1.22A; TaMin_C: -55°C; TaMax_C: 125°C; Cap_Case: D; AEC Category: Q200; SizeArea_mm2: 31.39; SizeAreaWB_mm2: 58.59; SizeX_mm: 7.3; SizeY_mm: 4.3; SizeZ_mm: 3.1
C92 = CMP-0011708-2: CAP, TA, 4.7 uF, 35 V, +/- 10%, 1.3 ohm, SMD; Manufacturer: Vishay-Sprague; Polarized: Y; CompType: Capacitor; Value: 4.7uF; U/M: EA; Cap_F: 4.7µF; Value1: 1.3 ohm; VDC_V: 35V; ESR_ohm: 1.3; IRMS_A: 3.4dA; TaMin_C: -55°C; TaMax_C: 125°C; Cap_Case: D; AEC Category: Q200; SizeAreaWB_mm2: 58.59; SizeArea_mm2: 31.39; SizeX_mm: 7.3; SizeY_mm: 4.3; SizeZ_mm: 3.1
C94 C95 = CMP-0084375-1: CAP, CERM, 1 µF, 16 V,+/- 20%, X5R, 0402; Manufacturer: MuRata; Polarized: N; CompType: Capacitor; Value: 1uF; U/M: EA; VDC_V: 16V; TaMin_C: -55°C; TaMax_C: 85°C; AEC Category: Q200; SizeArea_mm2: 0.5; SizeAreaWB_mm2: 3; SizeX_mm: 1; SizeZ_mm: 0.6
C96 C97 = CMP-0006259-2: CAP, CERM, 0.1 uF, 10 V, +/- 10%, X5R, 0402; Manufacturer: TDK; Polarized: N; Value: 0.1uF; U/M: EA; Cap_F: 100nF; Value1: Unknown; VDC_V: 10V; TaMin_C: -55°C; TaMax_C: 85°C; AEC Category: Q200; SizeArea_mm2: 0.5; SizeAreaWB_mm2: 3; SizeX_mm: 1; SizeZ_mm: 0.6
C103 C104 = CMP-0006606-2: CAP, CERM, 1000 pF, 25 V, +/- 10%, X5R, 0402; Manufacturer: MuRata; Polarized: N; Value: 1000pF; U/M: EA; Cap_F: 1nF; Value1: Unknown; VDC_V: 25V; TaMin_C: -55°C; TaMax_C: 85°C; AEC Category: Q200; SizeArea_mm2: 0.5; SizeAreaWB_mm2: 3; SizeX_mm: 1; SizeZ_mm: 0.6
C111 = CMP-0007110-5: CAP, CERM, 0.1 uF, 16 V, +/- 10%, X7R, 0603; Manufacturer: Samsung Electro-Mechanics; Polarized: N; Value: 0.1uF; U/M: EA; Cap_F: 100nF; Value1: Unknown; VDC_V: 16V; TaMin_C: -55°C; TaMax_C: 125°C; Cap_Case: 0603; AEC Category: Q200; SizeArea_mm2: 1.28; SizeAreaWB_mm2: 4.68; SizeX_mm: 1.6; SizeY_mm: 0.8; SizeZ_mm: 1
C112 = CMP-0006850-4: CAP, CERM, 0.01 uF, 50 V, +/- 5%, X7R, 0603; Manufacturer: Kemet; Polarized: N; Value: 0.01uF; U/M: EA; Cap_F: 10nF; Value1: Unknown; VDC_V: 50V; TaMin_C: -55°C; TaMax_C: 125°C; Cap_Case: 0603; AEC Category: Q200; SizeArea_mm2: 1.28; SizeAreaWB_mm2: 4.68; SizeX_mm: 1.6; SizeY_mm: 0.8; SizeZ_mm: 1
C113 = CMP-0006764-4: CAP, CERM, 1000 pF, 50 V, +/- 10%, C0G/NP0, 0603; Manufacturer: AVX; Polarized: N; Value: 1000pF; U/M: EA; Cap_F: 1nF; ESR_ohm: 0.048; Value1: 0.048 ohm; VDC_V: 50V; TaMin_C: -55°C; TaMax_C: 125°C; Cap_Case: 0603; AEC Category: Q200; SizeArea_mm2: 1.28; SizeAreaWB_mm2: 4.68; SizeX_mm: 1.6; SizeY_mm: 0.8; SizeZ_mm: 1
C116 = CMP-0007676-2: CAP, CERM, 1 uF, 16 V, +/- 10%, X5R, 0805; Manufacturer: AVX; Polarized: N; Value: 1uF; U/M: EA; Cap_F: 1µF; ESR_ohm: 0.012; Value1: 0.012 ohm; VDC_V: 16V; TaMin_C: -55°C; TaMax_C: 85°C; Cap_Case: 0805; AEC Category: Q200; SizeArea_mm2: 2.5; SizeAreaWB_mm2: 6.75; SizeX_mm: 2; SizeY_mm: 1.25; SizeZ_mm: 1.45
C117 = CMP-0007960-1: CAP, CERM, 4.7 uF, 10 V, +80/-20%, Y5V, 0805; Manufacturer: Yageo America; Polarized: N; Value: 4.7uF; U/M: EA; Cap_F: 4.7µF; Tolerance_%: 80%; Value1: Unknown; VDC_V: 10V; TaMin_C: -30°C; TaMax_C: 85°C; Cap_Case: 0805; AEC Category: Q200; SizeArea_mm2: 2.5; SizeAreaWB_mm2: 6.75; SizeX_mm: 2; SizeY_mm: 1.25; SizeZ_mm: 1.45
C118 = CMP-0007116-4: CAP, CERM, 27 pF, 50 V, +/- 1%, C0G/NP0, 0603; Manufacturer: Samsung Electro-Mechanics; Polarized: N; Value: 27pF; U/M: EA; Value1: Unknown; VDC_V: 50V; TaMin_C: -55°C; TaMax_C: 125°C; Cap_Case: 0603; AEC Category: Q200; SizeArea_mm2: 1.28; SizeAreaWB_mm2: 4.68; SizeX_mm: 1.6; SizeY_mm: 0.8; SizeZ_mm: 1
D4 = CMP-0028762-1: Diode, Schottky, 60 V, 1 A, AEC-Q101, SMA; Manufacturer: ON Semiconductor; U/M: EA; Vf_V: 5.1dV; Value: 60V; Value1: 1A; Value2: 0.51V; TJmax_C: 150°C; AEC Category: Q101; AEC Qualified: Y; Green_Lifecycle: Active; Green_REACh: Passed; SizeArea_mm2: 16.3228; SizeAreaWB_mm2: 37.3428; SizeX_mm: 5.59; SizeY_mm: 2.92; SizeZ_mm: 2.87
D5-D8 = CMP-0002917-1: LED, Green, SMD; Manufacturer: Everlight; Vf_V: 2.1V; Io_A: 20mA; Vr_V: 5V; Tjmax_C: 85°C; Value1: W; Angle: 140; U/M: EA
F1 = CMP-0003588-2: Fuse, 3 A, 32 VDC, SMD; Manufacturer: AVX; VDC_V: 32V; Irating_A: 3A; Rtyp_Ohm: 0.03; SizeAreaWB_mm2: 4.68; SizeArea_mm2: 1.28; SizeX_mm: 1.6; SizeY_mm: 0.8; SizeZ_mm: 1
J21-J23 J27 J28 J33-J36 = CMP-0075484-1: Header, 100mil, 3x1, Gold, TH; Manufacturer: Samtec; Green_REACh: Passed; CT: False; Green_Lifecycle: Active; CNHeader: True
J24 J29 = CMP-0055113-1: Terminal, Turret, TH, Double; Manufacturer: Keystone; CompType: Turret Terminal; CNHeader: FALSE; Green_Lifecycle: Active; Green_REACh: Passed
J25 = CMP-0075114-1: Power Jack, 2mm, R/A, TH; Manufacturer: CUI Inc.; PartNumber: PJ-037AH; CNHeader: False; Shrouded: N; Gender: Male; Row_Count: 1; Pitch_mm: 6
J26 = CMP-0075483-1: Header, 100mil, 2x1, Gold, TH; Manufacturer: Samtec; Green_REACh: Passed; CT: False; Green_Lifecycle: Active; CNHeader: True
J30 J31 = CMP-0055113-1: Terminal, Turret, TH, Double; PartNumber: 1502-2; Manufacturer: Keystone; CompType: Turret Terminal; CNHeader: FALSE; Green_Lifecycle: Active; Green_REACh: Passed
J32 = CMP-0055301-1: Connector, Receptacle, Micro-USB Type AB, R/A, Bottom Mount SMT; Manufacturer: Molex; CompType: USB; Gender: Female; CNHeader: FALSE; CT: TRUE; Green_Lifecycle: Active; Green_REACh: Passed
L1 L2 = CMP-0063209-1: Inductor, Shielded, Ferrite, 1 uH, 1.6 A, 0.115 ohm, SMD; Manufacturer: Vishay-Dale; Ind_H: 1µH; Imax_A: 1.6A; Irms: 1.6A @ 40C rise; Isat: 1.88A @ 30% inductance drop; DCR_ohm: 1.15d; AEC Category: Q200; Green_Lifecycle: Not Set; Green_REACh: Incomplete; SizeArea_mm2: 3.2; SizeAreaWB_mm2: 7.8; SizeX_mm: 2; SizeY_mm: 1.6; SizeZ_mm: 1
P1 = CMP-0075418-1: Header, 100mil, 8x2, Gold, TH; Manufacturer: Samtec; Pitch_mm: 2.54; Cert_VDE: N; Gender: Male; Cert_CSA: Y; Voltage_V: 550V; Green_REACh: Passed; Current_A: 6.3A; CT: False; Green_Lifecycle: Active; Row_Count: 2; CNHeader: True
R102 = CMP-0022451-4: RES, 4.22 k, 1%, 0.1 W, AEC-Q200 Grade 0, 0603; Manufacturer: Vishay-Dale; Value: 4.22k; Value_Code: 4k22; Power_W: 100mW; Value2: 0.1W; VDC_V: 75V; TempCo: 100 ppm/C; EIA_Code: E96; AEC Category: Q200; AEC Qualified: Y; AEC Grade: 0; SizeArea_mm2: 1.28; SizeX_mm: 1.6; SizeY_mm: 0.8; SizeZ_mm: 1
R103 = CMP-0023885-3: RES, 1.35 k, 0.1%, 0.1 W, 0603; Manufacturer: Yageo America; Power_W: 100mW; TempCo: 25 ppm/C; Value_Code: 1k35; U/M: EA; Value: 1.35k; EIA_Code: E192; SizeX_mm: 1.6; SizeY_mm: 0.8; SizeZ_mm: 1; Value2: 0.1W; SizeArea_mm2: 1.28; VDC_V: 75V; AEC Category: Q200
R104 R106 R113 R116 = CMP-0025958-3: RES, 10.0 k, 1%, 0.063 W, AEC-Q200 Grade 0, 0402; Manufacturer: Vishay-Dale; Value: 10.0k; Res_ohm: 10k; Value_Code: 10k0; Power_W: 63mW; Value2: 0.063W; VDC_V: 50V; TempCo: 100 ppm/C; EIA_Code: E96; AEC Category: Q200; AEC Qualified: Y; AEC Grade: 0; SizeArea_mm2: 0.5; SizeX_mm: 1; SizeZ_mm: 0.6
R105 R111 R115 = CMP-0020616-2: RES, 0, 5%, 0.125 W, 0805; Manufacturer: Panasonic; Value: 0; Value_Code: 0000; Power_W: 125mW; Value2: 0.125W; VDC_V: 150V; TempCo: 600 ppm/C; SizeArea_mm2: 2.5; SizeX_mm: 2; SizeY_mm: 1.25; SizeZ_mm: 1.45; EIA_Code: E24; U/M: EA; AEC Category: Q200
R107 = CMP-0026972-3: RES, 750, 5%, 0.063 W, AEC-Q200 Grade 0, 0402; Manufacturer: Vishay-Dale; Power_W: 63mW; TempCo: 200 ppm/C; Value_Code: 750R; Value: 750; EIA_Code: E24; SizeX_mm: 1; SizeY_mm: 0.5; SizeZ_mm: 0.6; Value2: 0.063W; AEC Qualified: Y; VDC_V: 50V; AEC Category: Q200; AEC Grade: 0
R108-R110 = CMP-0026934-3: RES, 470, 5%, 0.063 W, AEC-Q200 Grade 0, 0402; Manufacturer: Vishay-Dale; Value: 470; Value_Code: 470R; Power_W: 63mW; Value2: 0.063W; VDC_V: 50V; TempCo: 200 ppm/C; EIA_Code: E24; AEC Category: Q200; AEC Grade: 0; AEC Qualified: Y; SizeArea_mm2: 0.5; SizeX_mm: 1; SizeZ_mm: 0.6
R112 = CMP-0026908-3: RES, 33, 5%, 0.063 W, AEC-Q200 Grade 0, 0402; Manufacturer: Vishay-Dale; Value: 33; Value_Code: 33R0; Power_W: 63mW; Value2: 0.063W; VDC_V: 50V; TempCo: 200 ppm/C; EIA_Code: E24; AEC Category: Q200; AEC Qualified: Y; AEC Grade: 0; SizeArea_mm2: 0.5; SizeX_mm: 1; SizeZ_mm: 0.6
R114 = CMP-0022746-3: RES, 10.0 k, 1%, 0.1 W, 0603; Manufacturer: Yageo America; Value: 10.0k; Res_ohm: 10k; Value_Code: 10k0; Power_W: 100mW; Value2: 0.1W; VDC_V: 150V; TempCo: 200 ppm/C; EIA_Code: E96; U/M: EA; AEC Category: Q200; SizeArea_mm2: 1.28; SizeX_mm: 1.6; SizeY_mm: 0.8; SizeZ_mm: 1
R117 = CMP-0022114-4: RES, 1.13 k, 1%, 0.1 W, AEC-Q200 Grade 0, 0603; Manufacturer: Vishay-Dale; Value: 1.13k; Value_Code: 1k13; Power_W: 100mW; Value2: 0.1W; VDC_V: 75V; TempCo: 100 ppm/C; EIA_Code: E96; AEC Category: Q200; AEC Grade: 0; AEC Qualified: Y; SizeArea_mm2: 1.28; SizeX_mm: 1.6; SizeY_mm: 0.8; SizeZ_mm: 1
R118 R119 = CMP-0025885-3: RES, 0, 5%, 0.1 W, 0603; Manufacturer: Yageo America; Value: 0; Value_Code: 0000; Power_W: 100mW; Value2: 0.1W; VDC_V: 50V; TempCo: 200 ppm/C; EIA_Code: E24; U/M: EA; AEC Category: Q200; SizeArea_mm2: 1.28; SizeX_mm: 1.6; SizeY_mm: 0.8; SizeZ_mm: 1
R120 = CMP-0022454-4: RES, 4.53 k, 1%, 0.1 W, AEC-Q200 Grade 0, 0603; Manufacturer: Vishay-Dale; Value: 4.53k; Value_Code: 4k53; Power_W: 100mW; Value2: 0.1W; VDC_V: 75V; TempCo: 100 ppm/C; EIA_Code: E96; AEC Category: Q200; AEC Grade: 0; AEC Qualified: Y; SizeArea_mm2: 1.28; SizeX_mm: 1.6; SizeY_mm: 0.8; SizeZ_mm: 1
T2 = CMP-0013076-2: Coupled inductor, 5 A, 0.01 ohm, SMD; Manufacturer: TDK; DCR_ohm: 0.01
U6 = CMP-0036893-1: Single Output Fast Transient Response LDO, 1.5 A, Adjustable 1.21 to 20 V Output, 2.1 to 20 V Input, 5-pin DDPAK (KTT), -40 to 125 degC, Green (RoHS & no Sb/Br); Manufacturer: Texas Instruments; Iout(Max)(A): 1.5; Iq(Typ)(mA): 1; SubFamily: Single Channel LDO; Vdo(Typ)(mV): 340; Vin(Max)(V): 20; Vin(Min)(V): 2.1; Vout Adj(Min)(V): 1.21
U7 = CMP-0073832-4: Single Output LDO, 1A, Adj. (1.2 to 5.0V), Reverse Current Protection, DRV0006A (WSON-6); Manufacturer: Texas Instruments; Alternate PartNumber: TPS73733DRVT; SizeX_mm: 2; CompType: IC; SizeZ_mm: 0.8; SizeArea_mm2: 4; SizeAreaWB_mm2: 9; U/M: EA; Green_Lifecycle: Active; Green_REACh: Passed
U8 = CMP-0066782-5: 150-mA, 30-V, Ultra-Low IQ, Wide Input Low-Dropout Regulator with Reverse Current Protection, DRV0006A (WSON-6); Manufacturer: Texas Instruments; Alternate PartNumber: TPS70933DRVT; SizeX_mm: 2; CompType: IC; SizeZ_mm: 0.8; SizeArea_mm2: 4; SizeAreaWB_mm2: 9; U/M: EA; Green_Lifecycle: Active; Green_REACh: Passed
U9 = CMP-0036320-2: Single Output High PSRR LDO, 500 mA, Fixed 2.5 V Output, 2.7 to 6.5 V Input, with Low IQ, 8-pin SON (DRB), -40 to 125 degC, Green (RoHS & no Sb/Br); Manufacturer: Texas Instruments; Vin(Min)(V): 2.7; Vout Adj(Max)(V): 2.5; Vin(Max)(V): 6.5; Accuracy(%): 2; SubFamily: Single Channel LDO; Iq(Typ)(mA): 0.04; Iout(Max)(A): 0.5; Vdo(Typ)(mV): 280
U10 = CMP-0036362-3: Single Output LDO, 500 mA, Adjustable 0.8 to 3.6 V Output, 0.8 to 5.5 V Input, with Programmable Soft Start, 10-pin SON (DRC), -40 to 125 degC, Green (RoHS & no Sb/Br); Manufacturer: Texas Instruments; Accuracy(%): 2; Iout(Max)(A): 0.5; Iq(Typ)(mA): 1; Power Good: TRUE; Rating: Catalog; SubFamily: Single Channel LDO; Vdo(Typ)(mV): 50; Vin(Max)(V): 5.5; Vin(Min)(V): 0.8; Vout Adj(Max)(V): 3.6; AEC Category: Q200; AEC Qualified: N; CompType: IC; SizeArea_mm2: 9; SizeAreaWB_mm2: 16; SizeX_mm: 3

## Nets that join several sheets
AUX_IOVDD: HSDC038B_Configuration_Pins (12 pins), HSDC038B_DP83869 (8 pins), HSDC038B_Power_Supply (J33.2)
EARTH_GND: HSDC038B_Configuration_Pins (20 pins), HSDC038B_Hardware (M1.1), HSDC038B_Magnetics (15 pins)
FXVCCR: HSDC038B_Configuration_Pins (J3.15), HSDC038B_Power_Supply (C81.1 C82.1 C83.1 L2.2)
FXVCCT: HSDC038B_Configuration_Pins (J3.16), HSDC038B_Power_Supply (C74.1 C75.1 L1.2)
GND: HSDC038B_COMS (31 pins), HSDC038B_Configuration_Pins (35 pins), HSDC038B_DP83869 (70 pins), HSDC038B_Hardware (M2.1 M3.1 M4.1), HSDC038B_Magnetics (18 pins), HSDC038B_Power_Supply (81 pins)
MCU_VBUS: HSDC038B_COMS (C4.2 U1.65), HSDC038B_Power_Supply (J27.2)
MCU_VCC: HSDC038B_COMS (11 pins), HSDC038B_Power_Supply (J23.2)
VDDA1P0: HSDC038B_DP83869 (13 pins), HSDC038B_Power_Supply (R115.2)
VDDA1P8_AB: HSDC038B_DP83869 (R71.1 U2.13), HSDC038B_Power_Supply (R118.1)
VDDA1P8_CD: HSDC038B_DP83869 (R72.1 TP5.1 U2.48), HSDC038B_Power_Supply (R119.1)
VDDA2P5: HSDC038B_DP83869 (7 pins), HSDC038B_Power_Supply (R109.2 R111.2)
VDDIO: HSDC038B_DP83869 (11 pins), HSDC038B_Power_Supply (J33.1 R105.2 R110.2)
VFX: HSDC038B_DP83869 (J15.2), HSDC038B_Power_Supply (J26.1)
Cap_TD_A_N: HSDC038B_DP83869 (R64.2), HSDC038B_Magnetics (C56.2)
Cap_TD_A_P: HSDC038B_DP83869 (R63.2), HSDC038B_Magnetics (C58.2)
Cap_TD_B_N: HSDC038B_DP83869 (R66.2), HSDC038B_Magnetics (C53.2)
Cap_TD_B_P: HSDC038B_DP83869 (R65.2), HSDC038B_Magnetics (C55.2)
Cap_TD_C_N: HSDC038B_DP83869 (R68.2), HSDC038B_Magnetics (C50.2)
Cap_TD_C_P: HSDC038B_DP83869 (R67.2), HSDC038B_Magnetics (C52.2)
Cap_TD_D_N: HSDC038B_DP83869 (R70.2), HSDC038B_Magnetics (C47.2)
Cap_TD_D_P: HSDC038B_DP83869 (R69.2), HSDC038B_Magnetics (C48.2)
JTAG_TDI: HSDC038B_Configuration_Pins (R22.2), HSDC038B_DP83869 (J17.8 R92.1 U2.24)
LED_0: HSDC038B_Configuration_Pins (J2.2), HSDC038B_DP83869 (U2.47)
LED_1: HSDC038B_Configuration_Pins (J4.2), HSDC038B_DP83869 (U2.46)
LED_2: HSDC038B_Configuration_Pins (J7.2), HSDC038B_DP83869 (U2.45)
MDC_OB: HSDC038B_COMS (U1.46), HSDC038B_DP83869 (R84.1)
MDIO_OB: HSDC038B_COMS (U1.47), HSDC038B_DP83869 (R78.1)
RX_CLK: HSDC038B_Configuration_Pins (J6.1), HSDC038B_DP83869 (R61.2 U2.32)
RX_CTRL: HSDC038B_Configuration_Pins (J8.1), HSDC038B_DP83869 (R51.2 U2.38)
RX_D0: HSDC038B_Configuration_Pins (R33.1 R41.2), HSDC038B_DP83869 (R59.2 U2.33)
RX_D1: HSDC038B_Configuration_Pins (R40.1 R43.2), HSDC038B_DP83869 (R57.2 U2.34)
RX_D2: HSDC038B_Configuration_Pins (J10.1), HSDC038B_DP83869 (R55.2 U2.35)
RX_D3: HSDC038B_Configuration_Pins (J11.1), HSDC038B_DP83869 (R53.2 U2.36)
SGMII_SI_N: HSDC038B_Configuration_Pins (C15.2 R45.1), HSDC038B_DP83869 (U2.17)
SGMII_SI_P: HSDC038B_Configuration_Pins (C17.2 R47.1), HSDC038B_DP83869 (U2.16)
SGMII_SO_N: HSDC038B_Configuration_Pins (C12.2 R31.1), HSDC038B_DP83869 (U2.14)
SGMII_SO_P: HSDC038B_Configuration_Pins (C14.2 R38.1), HSDC038B_DP83869 (U2.15)
TD_A_N: HSDC038B_DP83869 (R64.1 U2.2), HSDC038B_Magnetics (T1.11 U5.2 U5.9)
TD_A_P: HSDC038B_DP83869 (R63.1 U2.1), HSDC038B_Magnetics (T1.12 U5.1 U5.10)
TD_B_N: HSDC038B_DP83869 (R66.1 U2.5), HSDC038B_Magnetics (T1.8 U5.5 U5.6)
TD_B_P: HSDC038B_DP83869 (R65.1 U2.4), HSDC038B_Magnetics (T1.9 U5.4 U5.7)
TD_C_N: HSDC038B_DP83869 (R68.1 U2.8), HSDC038B_Magnetics (T1.5 U4.2 U4.9)
TD_C_P: HSDC038B_DP83869 (R67.1 U2.7), HSDC038B_Magnetics (T1.6 U4.1 U4.10)
TD_D_N: HSDC038B_DP83869 (R70.1 U2.11), HSDC038B_Magnetics (T1.2 U4.5 U4.6)
TD_D_P: HSDC038B_DP83869 (R69.1 U2.10), HSDC038B_Magnetics (T1.3 U4.4 U4.7)
USB_N: HSDC038B_COMS (R16.2), HSDC038B_Power_Supply (J32.2)
USB_P: HSDC038B_COMS (R17.2), HSDC038B_Power_Supply (J32.3)

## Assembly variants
001: not fitted C12 C14 C15 C17 C37 C38 C39 C42 C43 C45 C47 C48 C50 C51 C53 C55 C56 C57 C58 C59 C60 C61 FID1 FID2 FID3 FID4 FID5 FID6 J5 J9 J12 J13 J14 J16 J17 J18 R23 R33 R40 R41 R43 R63 R64 R65 R66 R67 R68 R69 R70 R71 R72 R83 R85 R89 R92 R93 R98 R99 R116 R117 TP1 TP2 TP3 TP4 TP5 TP6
